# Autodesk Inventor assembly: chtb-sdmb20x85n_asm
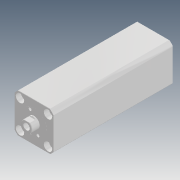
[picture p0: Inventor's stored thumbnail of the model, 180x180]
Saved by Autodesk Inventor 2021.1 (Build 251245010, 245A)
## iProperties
Company: Microsoft
Created: 2018-05
Part Number: chtb-sdmb20x85n_asm
Description: STEP AP214
Document SubType Name: Assembly
Designer: user
Title: chtb-sdmb20x85n_asm.STEP
Author: Windows
Revision Number: ÈÎºÎ
Sending System: SolidWorks 2015
Preprocessor: SwSTEP 2.0
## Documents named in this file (4)
- D:\Vault_2016\Projekty\Clamptek\Hydraulic\CHTB\CHTB-20\Inventor\CHTB-SDMB20x85N\chtb-sdmb20x85n_asm.iam
- D:\Vault_2016\Projekty\Clamptek\Hydraulic\CHTB\CHTB-20\Inventor\CHTB-SDMB20x85N\CHTB-SDMB20X85NBT.ipt
- D:\Vault_2016\Projekty\Clamptek\Hydraulic\CHTB\CHTB-20\Inventor\CHTB-SDMB20x85N\CHTB-SDMB20X85NHSG.ipt
- D:\Vault_2016\Projekty\Clamptek\Hydraulic\CHTB\CHTB-20\Inventor\CHTB-SDMB20x85N\QG_3.ipt
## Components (3 placed, 3 different names)
1. CHTB-SDMB20X85NBT_1
2. CHTB-SDMB20X85NHSG_2
3. QG_3_3
